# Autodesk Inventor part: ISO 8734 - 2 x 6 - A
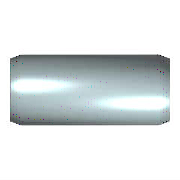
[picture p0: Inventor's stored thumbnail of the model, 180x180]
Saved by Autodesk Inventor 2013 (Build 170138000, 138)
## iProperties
Created: 2012-02
Part Number: ISO 8734 - 2 x 6 - A
Material: Steel
Description: Parallel Pin
Document SubType Name: Modeling
Standard: ISO 8734
Designer: rYan
Standards Organization: DIN
Language: en-US
Size Designation: 2 x 6 - A
Categories: <MemberInstance><Categories><Category DisplayName="Fasteners" InternalName="e4da775c-781d-43d5-af7c-5136215cf5a6" Mnemonic="FSTN"><Category DisplayName="Pins" I
Density: 7.85 g/cm^3
IsCustomPart: 0
Author: rYan
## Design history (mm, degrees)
sketch "Sketch"
  geometry: C1 r 1 at (0, 0); 1 further point
  constraints: 1 centre point, 1 coincident
  dimensions: "d1" = 2 diameter of C1 (= NND)
extrude "Body" new body sketch "Sketch" distance "d2" = 6 (= NLG); taper "d3" = 0 deg
body "Solid1"
chamfer "Chamfer1" distance "d4" = 0.35 (= PHH); stored, may be unused: angle "d5" = 15 deg (= FAWI), second distance "d11" = 0.35 (= PHH)
chamfer "Chamfer2" distance "d8" = 0.35 (= PHH); stored, may be unused: angle "d9" = 15 deg (= FAWI), second distance "d12" = 0.35 (= PHH)
other parameters: "NND" = 2 [user parameter; used in 1 equation term], "NLG" = 6 [user parameter; used in 1 equation term], "PHH" = 0.35 [user parameter; used in 5 equation terms], "FAWI" = 15 deg [user parameter; used in 2 equation terms], "d13" = 0, "d15" = 0, "d16" = 0, "PHH2" = 0.35 (= PHH) [user parameter], "FAWI2" = 15 deg [user parameter]
